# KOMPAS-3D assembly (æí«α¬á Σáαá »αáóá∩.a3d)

Referenced files in D:\МОДЕЛЬ ТАНКА Т90\СБОРКИ\сборка фара правая\: ограждение1.m3d, фара правая.m3d
Referenced files in D:\МОДЕЛЬ ТАНКА Т90\ДЕТАЛИ\ОБЩИЕ ДЕТАЛИ\: болт м1.m3d
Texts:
  Сборка фара правая
  stalker61
  Сплав АЛ8  ГОСТ 1583-93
